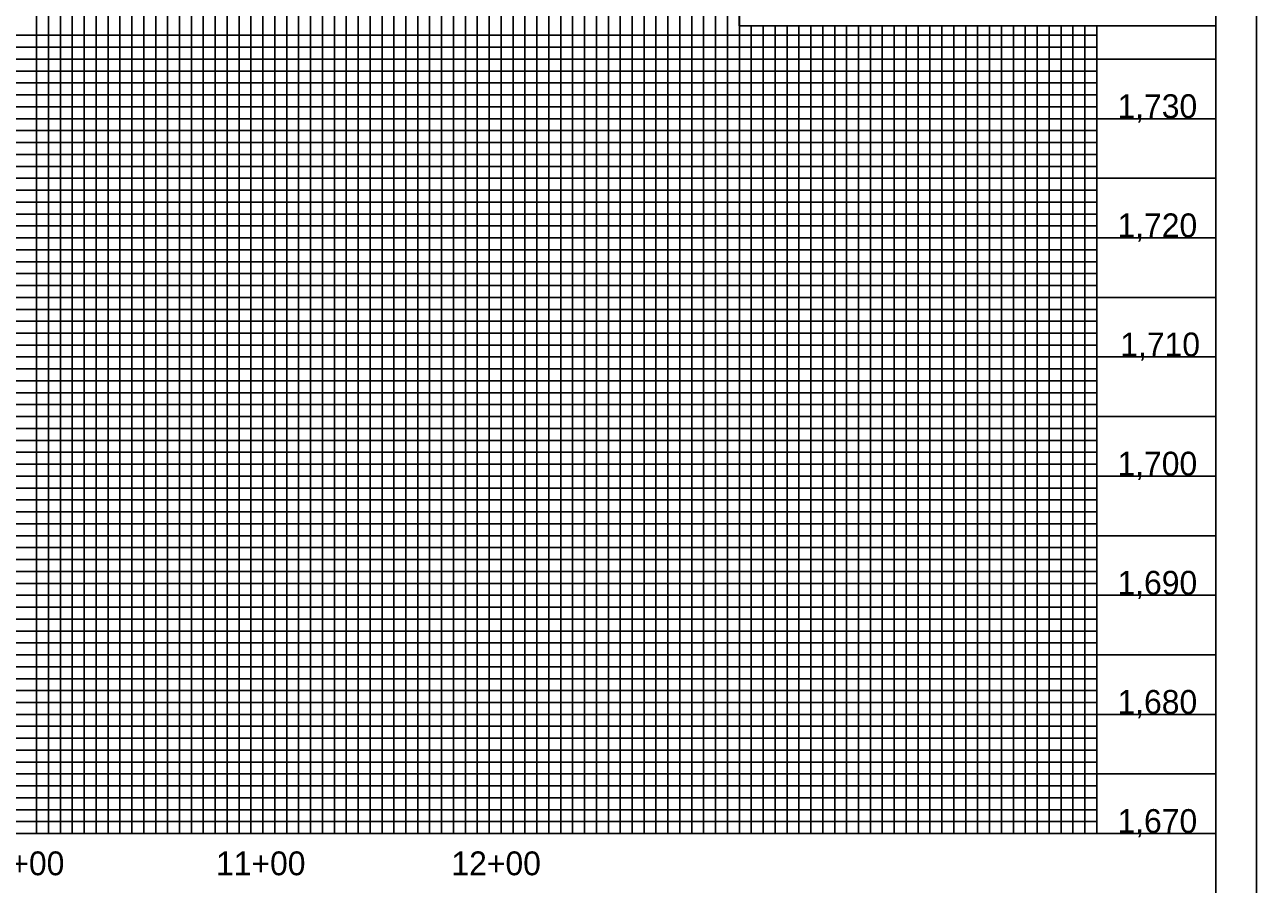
# Model space of a CAD drawing. Extents: x 505602 to 527661, y 418813 to 494436.
# Drawn here: x 506769 to 507286, y 483662 to 484023 of the extents above; entities that cross this region are included whole.
import ezdxf

# ---------------------------------------------------------------- set-up
doc = ezdxf.new("R2010")
doc.units = 0
for name, color, linetype in [('Exist Vertical Profile Vertical Axis Label', 7, 'Continuous'), ('Sheet Layout Profile Border Port 2', 7, 'Continuous'), ('Sheet Plot Border Outside CELL', 7, 'Continuous'), ('Sheet Profile CELL', 7, 'Continuous'), ('Sheet Profile Grid Major CELL', 7, 'Continuous'), ('Sheet Profile Grid Middle CELL', 7, 'Continuous'), ('Sheet Profile Grid Minor CELL', 7, 'Continuous'), ('Sheet Sticker Exception Certification CELL', 7, 'Continuous')]:
    doc.layers.add(name, color=color, linetype=linetype)

msp = doc.modelspace()

# ---------------------------------------------------------------- linework, layer by layer
at = {"layer": 'Sheet Layout Profile Border Port 2'}
msp.add_lwpolyline([(506719.08, 484183.71), (507069.08, 484183.71), (507069.08, 483683.71), (506719.08, 483683.71)], close=True, dxfattribs=at)
at = {"layer": 'Sheet Plot Border Outside CELL'}
msp.add_lwpolyline([(505602.08, 483108.71), (507286.08, 483108.71), (507286.08, 484208.71), (505602.08, 484208.71)], close=True, dxfattribs=at)
at = {"layer": 'Sheet Profile CELL'}
msp.add_line((505769.08, 483683.71), (507269.08, 483683.71), dxfattribs=at)
msp.add_lwpolyline([(507269.08, 484183.71), (505769.08, 484183.71), (505769.08, 483133.71), (507269.08, 483133.71)], close=True, dxfattribs=at)
at = {"layer": 'Sheet Profile Grid Major CELL'}
for points in [[(506769.08, 484183.71), (506819.08, 484183.71), (506819.08, 483683.71), (506869.08, 483683.71), (506869.08, 484183.71), (506919.08, 484183.71), (506919.08, 483683.71), (506969.08, 483683.71), (506969.08, 484183.71), (507019.08, 484183.71), (507019.08, 483683.71), (507069.08, 483683.71), (507069.08, 484183.71), (507095.38, 484183.71)], [(507219.08, 484022.66), (507219.08, 483683.71), (507269.08, 483683.71), (507269.08, 484033.71)], [(507119.08, 484022.66), (507119.08, 483683.71), (507169.08, 483683.71), (507169.08, 483683.71), (507169.08, 484022.66)], [(507269.08, 483983.71), (505769.08, 483983.71), (505769.08, 483933.71), (507269.08, 483933.71)], [(507269.08, 483883.71), (505769.08, 483883.71), (505769.08, 483833.71), (507269.08, 483833.71)], [(507269.08, 483783.71), (505769.08, 483783.71), (505769.08, 483783.71), (505769.08, 483733.71), (507269.08, 483733.71)]]:
    msp.add_lwpolyline(points, dxfattribs=at)
at = {"layer": 'Sheet Profile Grid Middle CELL'}
for points in [[(506744.08, 483683.71), (506794.08, 483683.71), (506794.08, 484183.71), (506844.08, 484183.71), (506844.08, 483683.71), (506894.08, 483683.71), (506894.08, 484183.71), (506944.08, 484183.71), (506944.08, 483683.71), (506994.08, 483683.71), (506994.08, 484183.71), (507044.08, 484183.71), (507044.08, 483683.71), (507094.08, 483683.71), (507094.08, 484022.66)], [(507094.08, 483946.51), (507094.08, 483683.71), (507144.08, 483683.71), (507144.08, 484022.66)], [(507144.08, 483946.51), (507144.08, 483683.71), (507194.08, 483683.71), (507194.08, 484022.66)], [(507269.08, 484008.71), (505769.08, 484008.71), (505769.08, 483958.71), (507094.08, 483958.71)], [(507094.08, 483958.71), (507269.08, 483958.71)], [(507269.08, 483908.71), (505769.08, 483908.71), (505769.08, 483858.71), (507269.08, 483858.71)], [(507269.08, 483808.71), (505769.08, 483808.71), (505769.08, 483758.71), (507269.08, 483758.71)], [(507269.08, 483708.71), (505769.08, 483708.71)]]:
    msp.add_lwpolyline(points, dxfattribs=at)
at = {"layer": 'Sheet Profile Grid Minor CELL'}
for p, q in [((505819.08, 484018.71), (507219.08, 484018.71)), ((507219.08, 483998.71), (505819.08, 483998.71)), ((505819.08, 483993.71), (507219.08, 483993.71)), ((507219.08, 483973.71), (505819.08, 483973.71)), ((505819.08, 483968.71), (507219.08, 483968.71)), ((507219.08, 483948.71), (505819.08, 483948.71)), ((505819.08, 483943.71), (507219.08, 483943.71)), ((507219.08, 483938.71), (505819.08, 483938.71)), ((505819.08, 483928.71), (507219.08, 483928.71)), ((507219.08, 483923.71), (505819.08, 483923.71)), ((505819.08, 483918.71), (507219.08, 483918.71)), ((507219.08, 483913.71), (505819.08, 483913.71)), ((505819.08, 483903.71), (507219.08, 483903.71)), ((507219.08, 483898.71), (505819.08, 483898.71)), ((505819.08, 483893.71), (507219.08, 483893.71)), ((507219.08, 483888.71), (505819.08, 483888.71)), ((505819.08, 483878.71), (507219.08, 483878.71)), ((507219.08, 483873.71), (505819.08, 483873.71)), ((505819.08, 483868.71), (507219.08, 483868.71)), ((507219.08, 483863.71), (505819.08, 483863.71)), ((505819.08, 483853.71), (507219.08, 483853.71)), ((507219.08, 483848.71), (505819.08, 483848.71)), ((505819.08, 483843.71), (507219.08, 483843.71)), ((507219.08, 483838.71), (505819.08, 483838.71)), ((505819.08, 483828.71), (507219.08, 483828.71)), ((507219.08, 483823.71), (505819.08, 483823.71)), ((505819.08, 483818.71), (507219.08, 483818.71)), ((507219.08, 483813.71), (505819.08, 483813.71)), ((505819.08, 483803.71), (507219.08, 483803.71)), ((507219.08, 483798.71), (505819.08, 483798.71)), ((507219.08, 483793.71), (505819.08, 483793.71)), ((507219.08, 483788.71), (505819.08, 483788.71)), ((505819.08, 483778.71), (507219.08, 483778.71)), ((507219.08, 483773.71), (505819.08, 483773.71)), ((505819.08, 483768.71), (507219.08, 483768.71)), ((507219.08, 483763.71), (505819.08, 483763.71)), ((505819.08, 483753.71), (507219.08, 483753.71)), ((507219.08, 483748.71), (505819.08, 483748.71)), ((505819.08, 483743.71), (507219.08, 483743.71)), ((507219.08, 483738.71), (505819.08, 483738.71)), ((505819.08, 483728.71), (507219.08, 483728.71)), ((507219.08, 483723.71), (505819.08, 483723.71)), ((505819.08, 483718.71), (507219.08, 483718.71)), ((507219.08, 483713.71), (505819.08, 483713.71)), ((505819.08, 483703.71), (507219.08, 483703.71)), ((507219.08, 483698.71), (505819.08, 483698.71)), ((505819.08, 483693.71), (507219.08, 483693.71))]:
    msp.add_line(p, q, dxfattribs=at)
for points in [[(506774.08, 484183.71), (506774.08, 483683.71), (506779.08, 483683.71), (506779.08, 484183.71)], [(506784.08, 484183.71), (506784.08, 483683.71), (506789.08, 483683.71), (506789.08, 484183.71)], [(506799.08, 484183.71), (506799.08, 483683.71), (506804.08, 483683.71), (506804.08, 484183.71)], [(506809.08, 484183.71), (506809.08, 483683.71), (506814.08, 483683.71), (506814.08, 484183.71)], [(506824.08, 484183.71), (506824.08, 483683.71), (506829.08, 483683.71), (506829.08, 484183.71)], [(506834.08, 484183.71), (506834.08, 483683.71), (506839.08, 483683.71), (506839.08, 484183.71)], [(506849.08, 484183.71), (506849.08, 483683.71), (506854.08, 483683.71), (506854.08, 484183.71)], [(506859.08, 484183.71), (506859.08, 483683.71), (506864.08, 483683.71), (506864.08, 484183.71)], [(506874.08, 484183.71), (506874.08, 483683.71), (506879.08, 483683.71), (506879.08, 484183.71)], [(506884.08, 484183.71), (506884.08, 483683.71), (506889.08, 483683.71), (506889.08, 484183.71)], [(506899.08, 484183.71), (506899.08, 483683.71), (506904.08, 483683.71), (506904.08, 484183.71)], [(506909.08, 484183.71), (506909.08, 483683.71), (506914.08, 483683.71), (506914.08, 484183.71)], [(506924.08, 484183.71), (506924.08, 483683.71), (506929.08, 483683.71), (506929.08, 484183.71)], [(506934.08, 484183.71), (506934.08, 483683.71), (506939.08, 483683.71), (506939.08, 484183.71)], [(506949.08, 484183.71), (506949.08, 483683.71), (506954.08, 483683.71), (506954.08, 484183.71)], [(506959.08, 484183.71), (506959.08, 483683.71)], [(506959.08, 483683.71), (506964.08, 483683.71), (506964.08, 484183.71)], [(506974.08, 484183.71), (506974.08, 483683.71), (506979.08, 483683.71), (506979.08, 484183.71)], [(506984.08, 484183.71), (506984.08, 483683.71), (506989.08, 483683.71), (506989.08, 484183.71)], [(506999.08, 484183.71), (506999.08, 483683.71), (507004.08, 483683.71), (507004.08, 484183.71)], [(507009.08, 484183.71), (507009.08, 483683.71), (507014.08, 483683.71), (507014.08, 484183.71)], [(507024.08, 484183.71), (507024.08, 483683.71), (507029.08, 483683.71), (507029.08, 484183.71)], [(507034.08, 484183.71), (507034.08, 483683.71), (507039.08, 483683.71), (507039.08, 484183.71)], [(507049.08, 484183.71), (507049.08, 483683.71), (507054.08, 483683.71), (507054.08, 484183.71)], [(507059.08, 484183.71), (507059.08, 483683.71), (507064.08, 483683.71), (507064.08, 484183.71)], [(507074.08, 484022.66), (507074.08, 483683.71), (507079.08, 483683.71), (507079.08, 484022.66)], [(507084.08, 484022.66), (507084.08, 483683.71), (507089.08, 483683.71), (507089.08, 484022.66)], [(507099.08, 484022.66), (507099.08, 483683.71), (507099.08, 483683.71), (507104.08, 483683.71), (507109.08, 483683.71), (507109.08, 484022.66)], [(507104.08, 484022.66), (507104.08, 483683.71)], [(507114.07, 484022.66), (507113.98, 483683.76), (507118.98, 483683.76), (507124.08, 483683.71), (507124.08, 484022.66)], [(507124.08, 483946.51), (507124.08, 483683.71), (507129.08, 483683.71), (507129.08, 484022.66)], [(507134.08, 484022.66), (507134.08, 483683.71), (507139.08, 483683.71), (507139.08, 484022.66)], [(507149.08, 484022.66), (507149.08, 483683.71), (507154.08, 483683.71), (507154.08, 484022.66)], [(507159.08, 484022.66), (507159.08, 483683.71), (507164.08, 483683.71), (507164.08, 484022.66)], [(507174.08, 484022.66), (507174.08, 483683.71), (507179.08, 483683.71), (507179.08, 484022.66)], [(507184.08, 484022.66), (507184.08, 483683.71), (507189.08, 483683.71), (507189.08, 484022.66)], [(507199.08, 484022.66), (507199.08, 483683.71), (507204.08, 483683.71), (507204.08, 484022.66)], [(507209.08, 484022.66), (507209.08, 483683.71), (507214.08, 483683.71), (507214.08, 484022.66)], [(507219.08, 484013.71), (505819.08, 484013.71), (505819.08, 484003.71), (507219.08, 484003.71)], [(507219.08, 483988.71), (505819.08, 483988.71), (505819.08, 483978.71), (507219.08, 483978.71)], [(507219.08, 483963.71), (505819.08, 483963.71), (505819.08, 483953.71), (507219.08, 483953.71)], [(507219.08, 483688.71), (505819.08, 483688.71)]]:
    msp.add_lwpolyline(points, dxfattribs=at)
at = {"layer": 'Sheet Sticker Exception Certification CELL'}
for p, q in [((507069.03, 484022.66), (507069.03, 484046.16)), ((507069.03, 484022.66), (507069.03, 484046.16)), ((507269.07, 484046.15), (507269.07, 484022.65)), ((507269.07, 484046.15), (507269.07, 484022.65)), ((507269.07, 484022.66), (507069.03, 484022.66)), ((507269.07, 484022.66), (507069.03, 484022.66))]:
    msp.add_line(p, q, dxfattribs=at)

# ---------------------------------------------------------------- texts
at = {"layer": 'Exist Vertical Profile Vertical Axis Label'}
for s, p in [('1,730', (507227.78, 483983.96)), ('1,720', (507227.78, 483933.96)), ('1,710', (507228.97, 483883.96)), ('1,700', (507227.78, 483833.96)), ('1,690', (507227.78, 483783.96)), ('1,680', (507227.78, 483733.96)), ('1,670', (507227.78, 483683.96)), ('10+00', (506748.21, 483666.21)), ('11+00', (506849.41, 483666.21)), ('12+00', (506948.21, 483666.21))]:
    msp.add_text(s, height=10, dxfattribs=at).set_placement(p)

doc.saveas('drawing.dxf')
